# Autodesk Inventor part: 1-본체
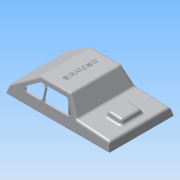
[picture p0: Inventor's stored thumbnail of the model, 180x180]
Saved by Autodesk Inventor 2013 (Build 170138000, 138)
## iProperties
Created: 2015-05
Part Number: 1-본체
Material: ABS 플라스틱
Document SubType Name: Modeling
Designer: Administrator
Density: 7.85 g/cm^3
Mass: 233.762 g
Surface Area: 297.913 cm^2
Volume: 29.7786 cm^3
Author: Administrator
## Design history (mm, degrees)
sketch "스케치1"
  geometry: L1 (61, -38)-(-61, -38); L2 (-61, -38)-(-61, 38); L3 (-61, 38)-(61, 38); L4 (61, 38)-(61, -38); L5 (61, -38)-(-61, 38); L6 (-61, -38)-(61, 38); 1 further point
  constraints: 12 end point, 2 midpoint, 2 parallel, 1 horizontal, 1 perpendicular
  dimensions: "d0" = 122 distance of L2.end L3.end; "d2" = 76 distance of L3.end L1.start
extrude "돌출1" new body sketch "스케치1" distance "d3" = 30; taper "d4" = -15 deg
node "작업 평면1"
sketch "스케치3"
  geometry: L1 (52.962, 30)-(-52.962, 30) reference; L2 (-61, 0)-(-52.962, 30) reference; L3 (61, 0)-(-61, 0) reference; L4 (61, 0)-(52.962, 30) reference; L5 (-58.588, 9)-(-19, 11.075); L6 (-19, 11.075)-(-7.174, 30); L7 (28.321, 30)-(58.321, 10); L8 (60.732, 1)-(59.732, 1); L9 (59.732, 1)-(59.732, 0); L10 (-60.732, 1)-(-59.732, 1); L11 (-59.732, 1)-(-59.732, 0); L12 (61, 0)-(52.962, 30) reference; 1 further point
  constraints: 14 end point, 8 point on line, 3 perpendicular, 1 parallel
  dimensions: "d23" = 9 distance from line of L3 L5.start; "d25" = 125 deg angle of L6 L5; "d27" = 1 distance of L10.start L10.end; "d28" = 1 distance of L10.end L11.end; "d29" = 1 distance of L8.start L8.end; "d30" = 1 distance of L8.end L9.end; "d31" = 30 horizontal distance of L7.start L7.end; "d32" = 20 vertical distance of L7.start L7.end; "d34" = 3 deg angle of L3 L5; "d83" = 42 horizontal distance of L5.end L2.start
extrude "돌출3" cut sketch "스케치3" stored distance "d35" = 31; taper "d36" = 0 deg
sketch "스케치5"
  geometry: L1 (-8.121, 22.588)-(-28.121, 22.588); L2 (-28.121, 22.588)-(-28.121, 48.588); L3 (-28.121, 48.588)-(-8.121, 48.588); L4 (-8.121, 48.588)-(-8.121, 22.588); L5 (-8.121, 22.588)-(-28.121, 48.588); L6 (-28.121, 22.588)-(-8.121, 48.588); L7 (2.879, 73.588)-(2.879, -2.412) reference; 3 further points
  constraints: 12 end point, 3 midpoint, 2 parallel, 1 horizontal, 1 horizontal alignment, 1 perpendicular
  dimensions: "d37" = 20 distance of L2.end L3.end; "d40" = 26 distance of L1.end L2.end; "d65" = 11 distance between parallel lines of L7 L4
extrude "돌출4" join sketch "스케치5" distance "d42" = 5; taper "d43" = -20 deg
feature "쉘1" dims "d44" = 2
sketch "스케치6"
  geometry: L1 (-4.403, 25)-(-10.908, 14.59); L2 (-8.364, 10)-(17.224, 10); L3 (20.224, 13)-(20.224, 22); L4 (17.224, 25)-(-4.403, 25); L5 (61, 0)-(58.321, 10) reference; L6 (58.321, 10)-(28.321, 30) reference; L7 (28.321, 30)-(-7.174, 30) reference; L8 (-7.174, 30)-(-19, 11.075) reference; L9 (-19, 11.075)-(-58.588, 9) reference; L10 (-61, 0)-(-58.588, 9) reference; L11 (61, 0)-(-61, 0) reference; L12 (-7.174, 30)-(-19, 11.075) reference; L13 (58.321, 10)-(28.321, 30) reference; L14 (21.307, 22)-(21.307, 13); L15 (24.307, 10)-(39.398, 10); L16 (41.062, 15.496)-(26.807, 25); L17 (26.807, 25)-(24.307, 25); A1 r 3 centre (39.398, 13) between (39.398, 10) and (41.062, 15.496); A2 r 3 centre (24.307, 22) between (24.307, 25) and (21.307, 22); A3 r 3 centre (24.307, 13) between (21.307, 13) and (24.307, 10); A4 r 3 centre (17.224, 22) between (20.224, 22) and (17.224, 25); A5 r 3 centre (17.224, 13) between (17.224, 10) and (20.224, 13); A6 r 3 centre (-8.364, 13) between (-10.908, 14.59) and (-8.364, 10); 6 further points
  constraints: 16 end point, 12 point on circle, 12 tangent, 10 point on line, 6 centre point, 4 equal radius, 4 perpendicular, 3 parallel, 2 collinear, 1 horizontal
  dimensions: "d46" = 34 distance of point (-13.776, 10) point (20.224, 10); "d48" = 15 vertical distance of L1.start point (-13.776, 10); "d54" = 5 distance between parallel lines of L8 L1; "d56" = 5 distance between parallel lines of L4 L7; "d79" = 5 distance between parallel lines of L6 L16; "d80" = 28 distance of point (21.307, 10) point (49.307, 10); "d81" = 3 radius of A1; "d82" = 3 radius of A2
extrude "돌출5" cut sketch "스케치6" stored distance "d57" = 5; taper "d58" = 0 deg
sketch "스케치10"
  geometry: L1 (61, -38)-(61, 38) reference; L2 (61, 38)-(-61, 38) reference; L3 (-61, 38)-(-61, -38) reference; L4 (-60, -37)-(-60, 37); L5 (-60, 37)-(60, 37); L6 (60, 37)-(60, -37); L7 (-60, -37)-(60, -37); L8 (-61, -38)-(61, -38) reference; 1 further point
  constraints: 8 end point, 1 perpendicular
  dimensions: "d66" = 1 distance between parallel lines of L2 L5; "d67" = 1 distance between parallel lines of L8 L7; "d68" = 1 distance between parallel lines of L4 L3; "d69" = 1 distance between parallel lines of L1 L6
extrude "돌출6" join sketch "스케치10" distance "d70" = 1; taper "d71" = 0 deg
sketch "스케치11"
  geometry: L1 (-60, 37)-(-60, -37) reference; L2 (-60, -37)-(60, -37) reference; L3 (60, -37)-(60, 37) reference; L4 (60, 37)-(-60, 37) reference; L5 (-59, 36)-(-59, -36); L6 (-59, -36)-(59, -36); L7 (59, -36)-(59, 36); L8 (59, 36)-(-59, 36); 1 further point
  constraints: 8 end point, 3 other
  dimensions: "d72" = 1 distance between parallel lines of L8 L4
extrude "돌출7" cut sketch "스케치11" distance "d73" = 1; taper "d74" = 0 deg
node "작업 평면2"
sketch "스케치12"
  geometry: L1 (-33.879, -9.78)-(-33.879, 9.78) reference; L2 (-33.879, 9.78)-(-47.42, 9.78) reference; L3 (-47.42, 9.78)-(-47.42, -9.78) reference; L4 (-47.42, -9.78)-(-33.879, -9.78) reference; C1 r 3 at (-40.65, 0); C2 r 3 at (-0.65, -22); C3 r 3 at (-0.65, 22); C4 r 3 at (39.35, 0); 3 further points
  constraints: 4 centre point, 3 equal radius, 2 horizontal alignment, 2 midpoint, 2 vertical alignment
  dimensions: "d85" = 40 horizontal distance of C3.centre C1.centre; "d87" = 40 horizontal distance of C4.centre C3.centre; "d89" = 6 diameter of C4; "d90" = 22 vertical distance of point (0, 0) C3.centre; "d91" = 22 vertical distance of point (0, 0) C2.centre
extrude "돌출8" join sketch "스케치12" stored distance "d92" = 1; taper "d93" = 0 deg
sketch "스케치15"
  geometry: L1 (-61, -38)-(-61, 38) reference; 2 further points
  constraints: 1 horizontal alignment, 1 other
  dimensions: "d103" = 50 distance from line of L1 point (-11, 0)
feature "엠보싱1" sketch "스케치15" dims "d0" = 122, "d2" = 76, "d104" = 0.5, "d105" = 0
fillet "모깎기1" dims "d101" = 3
fillet "모깎기2" dims "d102" = 3
fillet "모깎기4" dims "d107" = 3
fillet "모깎기5" dims "d108" = 3
fillet "모깎기6" dims "d109" = 3
fillet "모깎기7" dims "d110" = 12
fillet "모깎기10" dims "d113" = 3
fillet "모깎기11" dims "d114" = 3
sketch "스케치16"
  geometry: C1 r 3 at (0, 0) reference; C2 r 3 at (-80, 0) reference; C3 r 3 at (-40, 22) reference; C4 r 3 at (-40, -22) reference; 5 further points
  constraints: 4 coincident
hole "구멍1" sketch "스케치16" at (0, 0), (-40, 22), (-40, -22), (-80, 0) diameter "d115" = 3.242; stored, may be unused: countersink angle "d119" = 90 deg, drill point angle "d121" = 118 deg; dims "d116" = 9, "d117" = 4, "d118" = 2, "d120" = 11
node "솔리드1"
node "투영된 루프1"
node "투영된 루프2"
node "투영된 루프8"
node "투영된 루프15"
node "투영된 루프16"
node "투영된 루프17"
other parameters: "d22" = 0, "d84" = -1
